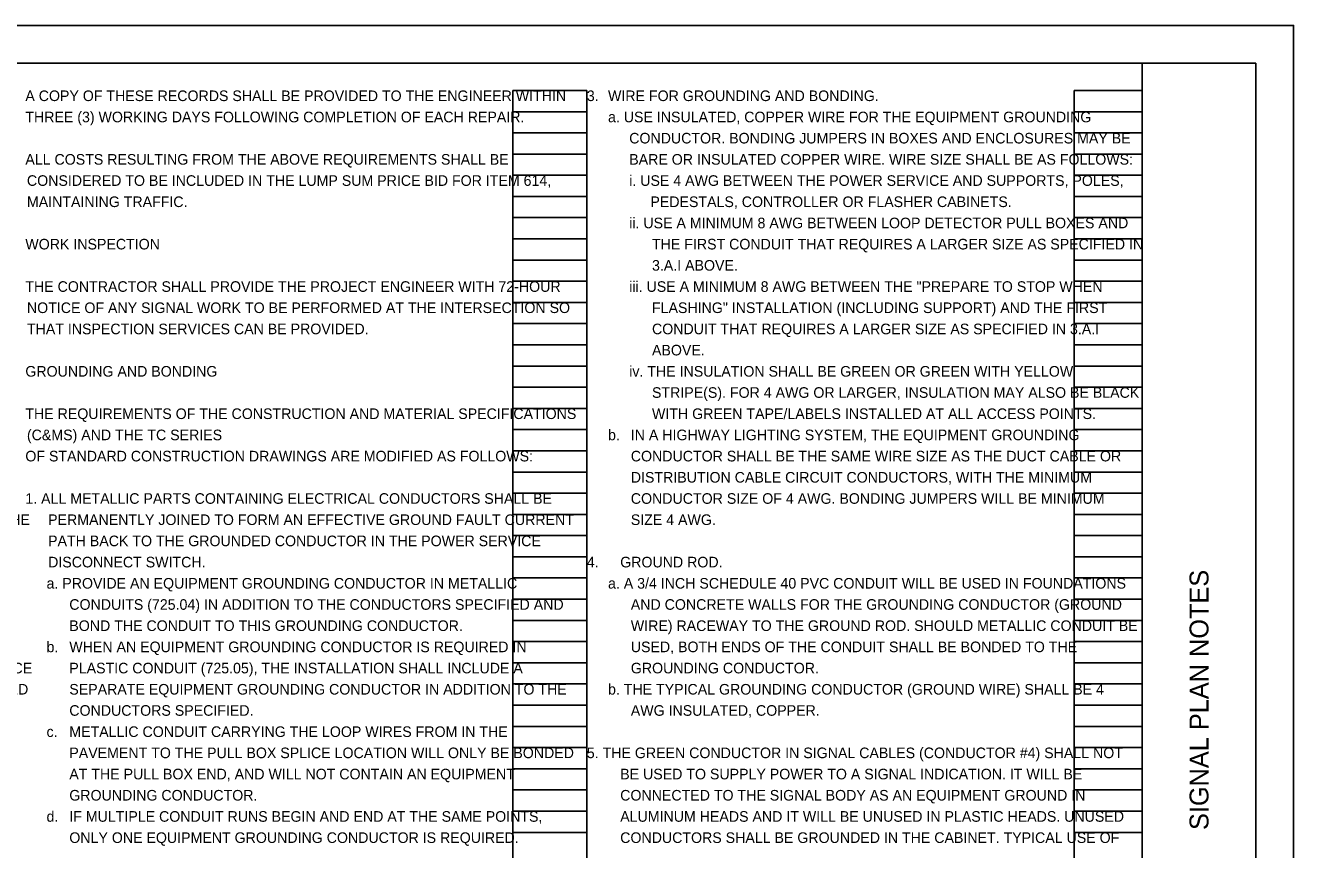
# Model space of a CAD drawing. Extents: x 0 to 34, y -30 to 22.
# Drawn here: x 17.24 to 34, y 11.11 to 22 of the extents above; entities that cross this region are included whole.
import ezdxf

# ---------------------------------------------------------------- set-up
doc = ezdxf.new("R2010")
doc.units = 0
for name, color, linetype in [('SH_Border', 7, 'Continuous'), ('SH_Cut_Line', 7, 'Continuous'), ('SH_Data', 7, 'Continuous'), ('SH_Text', 7, 'Continuous')]:
    doc.layers.add(name, color=color, linetype=linetype)

msp = doc.modelspace()

# ---------------------------------------------------------------- linework, layer by layer
at = {"layer": 'SH_Border'}
msp.add_line((32, 0.5), (32, 21.5), dxfattribs=at)
msp.add_lwpolyline([(1.5, 21.5), (33.5, 21.5), (33.5, 0.5), (1.5, 0.5)], close=True, dxfattribs=at)
at = {"layer": 'SH_Cut_Line'}
msp.add_lwpolyline([(0, 0), (34, 0), (34, 22), (0, 22)], close=True, dxfattribs=at)
at = {"layer": 'SH_Data'}
for p, q in [((23.68, 0.98), (23.68, 21.14)), ((23.68, 21.14), (24.66, 21.14)), ((24.66, 0.98), (24.66, 21.14)), ((31.1, 0.98), (31.1, 21.14)), ((31.1, 21.14), (32, 21.14)), ((32, 0.98), (32, 21.14)), ((23.68, 20.86), (24.66, 20.86)), ((31.1, 20.86), (32, 20.86)), ((23.68, 20.58), (24.66, 20.58)), ((31.1, 20.58), (32, 20.58)), ((23.68, 20.3), (24.66, 20.3)), ((31.1, 20.3), (32, 20.3)), ((23.68, 20.02), (24.66, 20.02)), ((31.1, 20.02), (32, 20.02)), ((23.68, 19.74), (24.66, 19.74)), ((31.1, 19.74), (32, 19.74)), ((23.68, 19.46), (24.66, 19.46)), ((31.1, 19.46), (32, 19.46)), ((23.68, 19.18), (24.66, 19.18)), ((31.1, 19.18), (32, 19.18)), ((23.68, 18.9), (24.66, 18.9)), ((31.1, 18.9), (32, 18.9)), ((23.68, 18.62), (24.66, 18.62)), ((31.1, 18.62), (32, 18.62)), ((23.68, 18.34), (24.66, 18.34)), ((31.1, 18.34), (32, 18.34)), ((23.68, 18.06), (24.66, 18.06)), ((31.1, 18.06), (32, 18.06)), ((23.68, 17.78), (24.66, 17.78)), ((31.1, 17.78), (32, 17.78)), ((23.68, 17.5), (24.66, 17.5)), ((31.1, 17.5), (32, 17.5)), ((23.68, 17.22), (24.66, 17.22)), ((31.1, 17.22), (32, 17.22)), ((23.68, 16.94), (24.66, 16.94)), ((31.1, 16.94), (32, 16.94)), ((23.68, 16.66), (24.66, 16.66)), ((31.1, 16.66), (32, 16.66)), ((23.68, 16.38), (24.66, 16.38)), ((31.1, 16.38), (32, 16.38)), ((23.68, 16.1), (24.66, 16.1)), ((31.1, 16.1), (32, 16.1)), ((23.68, 15.82), (24.66, 15.82)), ((31.1, 15.82), (32, 15.82)), ((23.68, 15.54), (24.66, 15.54)), ((31.1, 15.54), (32, 15.54)), ((23.68, 15.26), (24.66, 15.26)), ((31.1, 15.26), (32, 15.26)), ((23.68, 14.98), (24.66, 14.98)), ((31.1, 14.98), (32, 14.98)), ((23.68, 14.7), (24.66, 14.7)), ((31.1, 14.7), (32, 14.7)), ((23.68, 14.42), (24.66, 14.42)), ((31.1, 14.42), (32, 14.42)), ((23.68, 14.14), (24.66, 14.14)), ((31.1, 14.14), (32, 14.14)), ((23.68, 13.86), (24.66, 13.86)), ((31.1, 13.86), (32, 13.86)), ((23.68, 13.58), (24.66, 13.58)), ((31.1, 13.58), (32, 13.58)), ((23.68, 13.3), (24.66, 13.3)), ((31.1, 13.3), (32, 13.3)), ((23.68, 13.02), (24.66, 13.02)), ((31.1, 13.02), (32, 13.02)), ((23.68, 12.74), (24.66, 12.74)), ((31.1, 12.74), (32, 12.74)), ((23.68, 12.46), (24.66, 12.46)), ((31.1, 12.46), (32, 12.46)), ((23.68, 12.18), (24.66, 12.18)), ((31.1, 12.18), (32, 12.18)), ((23.68, 11.9), (24.66, 11.9)), ((31.1, 11.9), (32, 11.9)), ((23.68, 11.62), (24.66, 11.62)), ((31.1, 11.62), (32, 11.62)), ((23.68, 11.34), (24.66, 11.34)), ((31.1, 11.34), (32, 11.34))]:
    msp.add_line(p, q, dxfattribs=at)

# ---------------------------------------------------------------- texts
msp.add_text('SIGNAL PLAN NOTES', height=0.25, rotation=90, dxfattribs=at).set_placement((32.875, 11.371))
at = {"layer": 'SH_Text'}
for s, p in [('A COPY OF THESE RECORDS SHALL BE PROVIDED TO THE ENGINEER WITHIN ', (17.24, 21)), ('3.', (24.66, 21)), ('WIRE FOR GROUNDING AND BONDING.', (24.94, 21)), ('THREE (3) WORKING DAYS FOLLOWING COMPLETION OF EACH REPAIR.', (17.24, 20.72)), ('a. USE INSULATED, COPPER WIRE FOR THE EQUIPMENT GROUNDING ', (24.94, 20.72)), ('CONDUCTOR. BONDING JUMPERS IN BOXES AND ENCLOSURES MAY BE ', (25.22, 20.44)), ('ALL COSTS RESULTING FROM THE ABOVE REQUIREMENTS SHALL BE ', (17.24, 20.16)), ('BARE OR INSULATED COPPER WIRE. WIRE SIZE SHALL BE AS FOLLOWS:', (25.22, 20.16)), ('CONSIDERED TO BE INCLUDED IN THE LUMP SUM PRICE BID FOR ITEM 614, ', (17.261, 19.88)), ('i. USE 4 AWG BETWEEN THE POWER SERVICE AND SUPPORTS, POLES, ', (25.22, 19.88)), ('MAINTAINING TRAFFIC.', (17.261, 19.6)), ('PEDESTALS, CONTROLLER OR FLASHER CABINETS.', (25.5, 19.6)), ('ii. USE A MINIMUM 8 AWG BETWEEN LOOP DETECTOR PULL BOXES AND ', (25.22, 19.32)), ('WORK INSPECTION', (17.24, 19.04)), ('THE FIRST CONDUIT THAT REQUIRES A LARGER SIZE AS SPECIFIED IN ', (25.521, 19.04)), ('3.A.I ABOVE.', (25.521, 18.76)), ('THE CONTRACTOR SHALL PROVIDE THE PROJECT ENGINEER WITH 72-HOUR ', (17.24, 18.48)), ('iii. USE A MINIMUM 8 AWG BETWEEN THE "PREPARE TO STOP WHEN ', (25.22, 18.48)), ('NOTICE OF ANY SIGNAL WORK TO BE PERFORMED AT THE INTERSECTION SO ', (17.261, 18.2)), ('FLASHING" INSTALLATION (INCLUDING SUPPORT) AND THE FIRST ', (25.521, 18.2)), ('THAT INSPECTION SERVICES CAN BE PROVIDED.', (17.261, 17.92)), ('CONDUIT THAT REQUIRES A LARGER SIZE AS SPECIFIED IN 3.A.I ', (25.521, 17.92)), ('ABOVE.', (25.521, 17.64)), ('GROUNDING AND BONDING', (17.24, 17.36)), ('iv. THE INSULATION SHALL BE GREEN OR GREEN WITH YELLOW ', (25.22, 17.36)), ('STRIPE(S). FOR 4 AWG OR LARGER, INSULATION MAY ALSO BE BLACK ', (25.521, 17.08)), ('THE REQUIREMENTS OF THE CONSTRUCTION AND MATERIAL SPECIFICATIONS ', (17.24, 16.8)), ('WITH GREEN TAPE/LABELS INSTALLED AT ALL ACCESS POINTS.', (25.521, 16.8)), ('(C&MS) AND THE TC SERIES', (17.261, 16.52)), ('b.', (24.94, 16.52)), ('IN A HIGHWAY LIGHTING SYSTEM, THE EQUIPMENT GROUNDING ', (25.241, 16.52)), ('OF STANDARD CONSTRUCTION DRAWINGS ARE MODIFIED AS FOLLOWS:', (17.24, 16.24)), ('CONDUCTOR SHALL BE THE SAME WIRE SIZE AS THE DUCT CABLE OR ', (25.241, 16.24)), ('DISTRIBUTION CABLE CIRCUIT CONDUCTORS, WITH THE MINIMUM ', (25.241, 15.96)), ('1. ALL METALLIC PARTS CONTAINING ELECTRICAL CONDUCTORS SHALL BE ', (17.24, 15.68)), ('CONDUCTOR SIZE OF 4 AWG. BONDING JUMPERS WILL BE MINIMUM ', (25.241, 15.68)), ('COMPENSATION FOR THIS WORK FROM THOSE PARTIES RESPONSIBLE FOR THE ', (9.82, 15.4)), ('PERMANENTLY JOINED TO FORM AN EFFECTIVE GROUND FAULT CURRENT ', (17.541, 15.4)), ('SIZE 4 AWG.', (25.241, 15.4)), ('PATH BACK TO THE GROUNDED CONDUCTOR IN THE POWER SERVICE ', (17.541, 15.12)), ('DISCONNECT SWITCH.', (17.541, 14.84)), ('4.', (24.66, 14.84)), ('GROUND ROD.', (25.101, 14.84)), ('a. PROVIDE AN EQUIPMENT GROUNDING CONDUCTOR IN METALLIC ', (17.52, 14.56)), ('a. A 3/4 INCH SCHEDULE 40 PVC CONDUIT WILL BE USED IN FOUNDATIONS ', (24.94, 14.56)), ('CONDUITS (725.04) IN ADDITION TO THE CONDUCTORS SPECIFIED AND ', (17.821, 14.28)), ('AND CONCRETE WALLS FOR THE GROUNDING CONDUCTOR (GROUND ', (25.241, 14.28)), ('BOND THE CONDUIT TO THIS GROUNDING CONDUCTOR.', (17.821, 14)), ('WIRE) RACEWAY TO THE GROUND ROD. SHOULD METALLIC CONDUIT BE ', (25.241, 14)), ('b.', (17.52, 13.72)), ('WHEN AN EQUIPMENT GROUNDING CONDUCTOR IS REQUIRED IN ', (17.821, 13.72)), ('USED, BOTH ENDS OF THE CONDUIT SHALL BE BONDED TO THE ', (25.241, 13.72)), ('SUBSEQUENT BILLINGS TO THE STATE OR THE CITY OF LYNDHURST FOR POLICE ', (9.82, 13.44)), ('PLASTIC CONDUIT (725.05), THE INSTALLATION SHALL INCLUDE A ', (17.821, 13.44)), ('GROUNDING CONDUCTOR.', (25.241, 13.44)), ('SERVICES AND MAINTENANCE SERVICES BY CITY FORCES SHALL BE DEDUCTED ', (9.82, 13.16)), ('SEPARATE EQUIPMENT GROUNDING CONDUCTOR IN ADDITION TO THE ', (17.821, 13.16)), ('b. THE TYPICAL GROUNDING CONDUCTOR (GROUND WIRE) SHALL BE 4 ', (24.94, 13.16)), ('CONDUCTORS SPECIFIED.', (17.821, 12.88)), ('AWG INSULATED, COPPER.', (25.241, 12.88)), ('METALLIC CONDUIT CARRYING THE LOOP WIRES FROM IN THE ', (17.821, 12.6)), ('c.', (17.52, 12.6)), ('PAVEMENT TO THE PULL BOX SPLICE LOCATION WILL ONLY BE BONDED ', (17.821, 12.32)), ('5. THE GREEN CONDUCTOR IN SIGNAL CABLES (CONDUCTOR #4) SHALL NOT ', (24.66, 12.32)), ('AT THE PULL BOX END, AND WILL NOT CONTAIN AN EQUIPMENT ', (17.821, 12.04)), ('BE USED TO SUPPLY POWER TO A SIGNAL INDICATION. IT WILL BE ', (25.101, 12.04)), ('GROUNDING CONDUCTOR.', (17.821, 11.76)), ('CONNECTED TO THE SIGNAL BODY AS AN EQUIPMENT GROUND IN ', (25.101, 11.76)), ('d.', (17.52, 11.48)), ('IF MULTIPLE CONDUIT RUNS BEGIN AND END AT THE SAME POINTS, ', (17.821, 11.48)), ('ALUMINUM HEADS AND IT WILL BE UNUSED IN PLASTIC HEADS. UNUSED ', (25.101, 11.48)), ('ONLY ONE EQUIPMENT GROUNDING CONDUCTOR IS REQUIRED.', (17.821, 11.2)), ('CONDUCTORS SHALL BE GROUNDED IN THE CABINET. TYPICAL USE OF ', (25.101, 11.2))]:
    msp.add_text(s, height=0.14, dxfattribs=at).set_placement(p)

doc.saveas('drawing.dxf')
